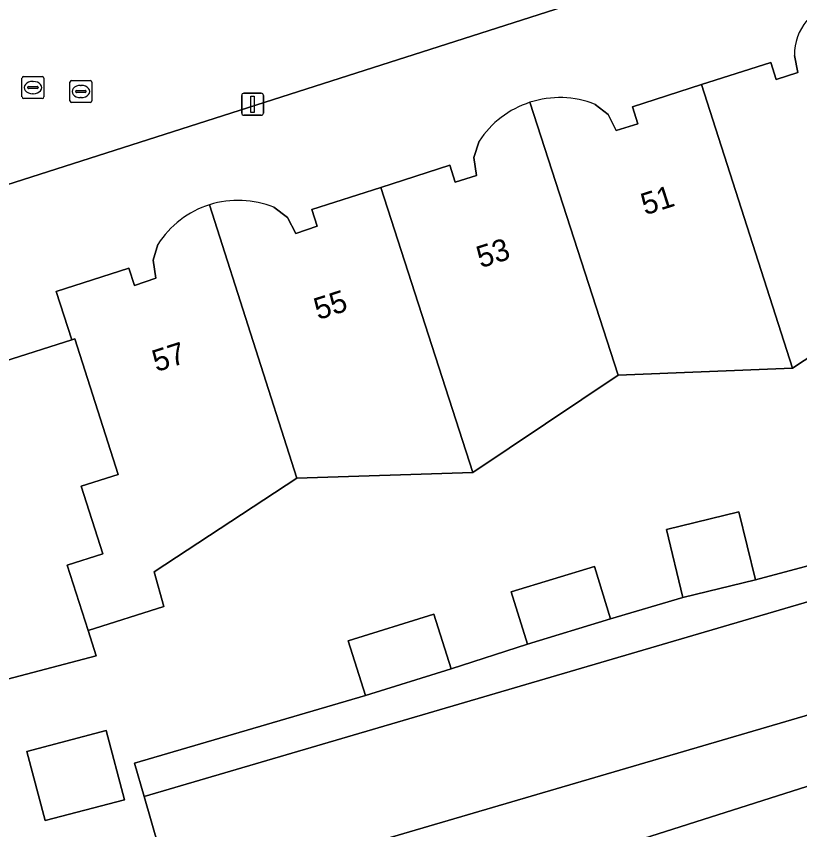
# Model space of a CAD drawing. Extents: x 159499 to 160349, y 382524 to 383273.
# Drawn here: x 159667.59 to 159703.39, y 382799.52 to 382836.7 of the extents above; entities that cross this region are included whole.
import ezdxf

# ---------------------------------------------------------------- set-up
doc = ezdxf.new("R2010")
doc.units = 0
for name, color, linetype in [('IMGEO_Erf', 7, 'Continuous'), ('IMGEO_Groenvoorziening', 7, 'Continuous'), ('IMGEO_Lichtmast', 7, 'Continuous'), ('IMGEO_Pand', 7, 'Continuous'), ('IMGEO_Pand_nummerreeks', 7, 'Continuous'), ('IMGEO_Rijbaan_lokaal_open', 7, 'Continuous'), ('IMGEO_Rioolput', 7, 'Continuous'), ('IMGEO_Voetpad_open', 7, 'Continuous')]:
    doc.layers.add(name, color=color, linetype=linetype)

msp = doc.modelspace()

# ---------------------------------------------------------------- linework, layer by layer
at = {"layer": 'IMGEO_Erf'}
for points in [[(159706.174, 382845.013), (159707.207, 382841.819), (159705.912, 382841.405), (159664.868, 382828.266), (159663.864, 382831.383), (159666.542, 382832.265), (159661.739, 382847.267), (159659.033, 382846.414), (159658.047, 382849.524), (159699.119, 382862.705), (159700.405, 382863.118), (159700.812, 382861.848)], [(159660.525, 382835.656), (159660.06, 382835.05), (159659.319, 382834.671), (159659.644, 382833.689), (159660.417, 382833.93), (159661.452, 382830.613), (159656.347, 382828.991), (159657.362, 382825.93), (159658.83, 382826.406), (159662.712, 382824.41), (159666.599, 382822.412), (159667.071, 382820.931), (159670.133, 382821.912), (159669.419, 382824.112), (159672.736, 382825.178), (159672.993, 382824.399), (159673.966, 382824.727), (159673.846, 382825.549), (159674.066, 382826.268)], [(159707.609, 382835.645), (159708.389, 382833.209), (159709.618, 382829.381), (159710.852, 382829.78), (159711.62, 382826.368), (159709.687, 382825.745), (159709.894, 382825.104), (159703.068, 382820.615), (159695.103, 382820.291), (159688.451, 382815.846), (159680.409, 382815.596)], [(159694.044, 382832.671), (159694.639, 382832.203), (159695.009, 382831.47), (159695.989, 382831.786), (159695.755, 382832.562), (159698.909, 382833.574), (159702.064, 382834.586), (159702.321, 382833.811), (159703.309, 382834.124), (159703.146, 382834.908)], [(159679.369, 382827.966), (159679.991, 382827.497), (159680.368, 382826.773), (159681.349, 382827.105), (159681.104, 382827.867), (159684.248, 382828.877), (159687.411, 382829.894), (159687.648, 382829.112), (159688.624, 382829.415), (159688.5, 382830.239), (159688.738, 382830.986)], [(159680.409, 382815.596), (159673.89, 382811.313), (159674.339, 382809.721), (159670.881, 382808.621), (159671.251, 382807.474), (159666.907, 382806.328), (159665.465, 382812.52)], [(159707.693, 382805.912), (159674.81, 382796.272), (159673.434, 382801.05), (159672.996, 382802.571), (159683.545, 382805.66), (159682.766, 382808.151), (159686.68, 382809.374), (159687.458, 382806.883), (159690.946, 382808.003), (159690.213, 382810.393), (159694.007, 382811.556), (159694.74, 382809.166), (159698.054, 382810.135), (159697.297, 382813.244), (159700.608, 382814.05), (159701.365, 382810.94), (159705.812, 382812.13)], [(159682.294, 382794.673), (159705.767, 382802.152), (159710.531, 382803.67), (159711.953, 382799.207), (159726.792, 382803.935), (159729.084, 382796.741)]]:
    msp.add_lwpolyline(points, dxfattribs=at)
msp.add_lwpolyline([(159668.916, 382799.943), (159668.084, 382803.101), (159671.699, 382804.055), (159672.532, 382800.897)], close=True, dxfattribs=at)
for centre, radius, start, end in [((159705.588, 382834.927), 2.442, 140.0081, 180.4376), ((159692.426, 382828.578), 4.401, 68.4311, 107.9903), ((159692.424, 382828.572), 4.406, 107.937, 146.7806), ((159677.732, 382823.945), 4.34, 107.475, 147.6411), ((159677.734, 382823.941), 4.344, 67.8876, 107.4767)]:
    msp.add_arc(centre, radius, start, end, dxfattribs=at)
at = {"layer": 'IMGEO_Groenvoorziening'}
msp.add_lwpolyline([(159742.845, 382815.409), (159741.322, 382820.139), (159729.3, 382816.347), (159706.393, 382810.712), (159673.434, 382801.05), (159674.81, 382796.272), (159707.693, 382805.912), (159730.6, 382811.547)], close=True, dxfattribs=at)
at = {"layer": 'IMGEO_Lichtmast'}
for p, q in [((159677.894, 382832.276), (159677.894, 382833.076)), ((159677.894, 382833.076), (159677.894, 382832.276)), ((159677.994, 382833.176), (159678.784, 382833.176)), ((159678.784, 382833.176), (159677.994, 382833.176)), ((159678.884, 382833.076), (159678.884, 382832.276)), ((159678.884, 382832.276), (159678.884, 382833.076)), ((159678.784, 382832.176), (159677.994, 382832.176)), ((159677.994, 382832.176), (159678.784, 382832.176))]:
    msp.add_line(p, q, dxfattribs=at)
msp.add_lwpolyline([(159678.314, 382833.051), (159678.464, 382833.051), (159678.464, 382832.301), (159678.314, 382832.301), (159678.314, 382833.051)], dxfattribs=at)
for centre, start, end in [((159677.994, 382833.076), 90, 180), ((159677.994, 382833.076), 90, 180), ((159678.784, 382833.076), 0, 90), ((159678.784, 382833.076), 360, 90), ((159677.994, 382832.276), 180, 270), ((159677.994, 382832.276), 180, 270), ((159678.784, 382832.276), 270, 0), ((159678.784, 382832.276), 270, 0)]:
    msp.add_arc(centre, 0.1, start, end, dxfattribs=at)
at = {"layer": 'IMGEO_Pand'}
for points in [[(159703.146, 382834.908), (159703.309, 382834.124), (159702.321, 382833.811), (159702.064, 382834.586), (159698.909, 382833.574), (159703.068, 382820.615), (159709.894, 382825.104), (159709.687, 382825.745), (159708.618, 382829.058), (159709.618, 382829.381), (159708.389, 382833.209)], [(159691.067, 382832.764), (159695.103, 382820.291), (159703.068, 382820.615), (159698.909, 382833.574), (159695.755, 382832.562), (159695.989, 382831.786), (159695.009, 382831.47), (159694.639, 382832.203), (159694.044, 382832.671)], [(159688.738, 382830.986), (159688.5, 382830.239), (159688.624, 382829.415), (159687.648, 382829.112), (159687.411, 382829.894), (159684.248, 382828.877), (159688.451, 382815.846), (159695.103, 382820.291), (159691.067, 382832.764)], [(159676.429, 382828.085), (159680.409, 382815.596), (159688.451, 382815.846), (159684.248, 382828.877), (159681.104, 382827.867), (159681.349, 382827.105), (159680.368, 382826.773), (159679.991, 382827.497), (159679.369, 382827.966)], [(159674.066, 382826.268), (159673.846, 382825.549), (159673.966, 382824.727), (159672.993, 382824.399), (159672.736, 382825.178), (159669.419, 382824.112), (159670.133, 382821.912), (159670.276, 382821.958), (159672.248, 382815.759), (159670.561, 382815.223), (159671.543, 382812.138), (159669.914, 382811.62), (159670.881, 382808.621), (159674.339, 382809.721), (159673.89, 382811.313), (159680.409, 382815.596), (159676.429, 382828.085)], [(159665.465, 382812.52), (159666.907, 382806.328), (159671.251, 382807.474), (159670.881, 382808.621), (159669.914, 382811.62), (159671.543, 382812.138), (159670.561, 382815.223), (159672.248, 382815.759), (159670.276, 382821.958), (159670.133, 382821.912), (159667.071, 382820.931), (159666.599, 382822.412), (159662.712, 382824.41), (159657.049, 382813.325)], [(159729.084, 382796.741), (159726.792, 382803.935), (159711.953, 382799.207), (159710.531, 382803.67), (159705.767, 382802.152), (159682.294, 382794.673)]]:
    msp.add_lwpolyline(points, dxfattribs=at)
for points in [[(159698.054, 382810.135), (159701.365, 382810.94), (159700.608, 382814.05), (159697.297, 382813.244)], [(159690.946, 382808.003), (159694.74, 382809.166), (159694.007, 382811.556), (159690.213, 382810.393)], [(159683.545, 382805.66), (159687.458, 382806.883), (159686.68, 382809.374), (159682.766, 382808.151)], [(159668.916, 382799.943), (159672.532, 382800.897), (159671.699, 382804.055), (159668.084, 382803.101)]]:
    msp.add_lwpolyline(points, close=True, dxfattribs=at)
for centre, radius, start, end in [((159705.588, 382834.927), 2.442, 140.0081, 180.4376), ((159692.426, 382828.578), 4.401, 68.4311, 107.9903), ((159692.424, 382828.572), 4.406, 107.937, 146.7806), ((159677.732, 382823.945), 4.34, 107.475, 147.6411), ((159677.734, 382823.941), 4.344, 67.8876, 107.4767)]:
    msp.add_arc(centre, radius, start, end, dxfattribs=at)
at = {"layer": 'IMGEO_Rijbaan_lokaal_open'}
msp.add_lwpolyline([(159699.712, 382860.799), (159699.119, 382862.705), (159658.047, 382849.524), (159659.033, 382846.414), (159661.739, 382847.267), (159666.542, 382832.265), (159663.864, 382831.383), (159664.868, 382828.266), (159705.912, 382841.405), (159704.996, 382844.273)], dxfattribs=at)
at = {"layer": 'IMGEO_Rioolput'}
for p, q in [((159667.856, 382833.012), (159667.856, 382833.864)), ((159667.931, 382833.938), (159668.783, 382833.938)), ((159668.344, 382833.718), (159668.369, 382833.718)), ((159668.857, 382833.864), (159668.857, 382833.012)), ((159670.046, 382832.833), (159670.046, 382833.685)), ((159670.121, 382833.759), (159670.973, 382833.759)), ((159671.047, 382833.685), (159671.047, 382832.833)), ((159668.115, 382833.432), (159668.115, 382833.444)), ((159668.553, 382833.395), (159668.155, 382833.395)), ((159668.158, 382833.481), (159668.556, 382833.481)), ((159668.599, 382833.444), (159668.599, 382833.432)), ((159670.305, 382833.253), (159670.305, 382833.265)), ((159670.348, 382833.302), (159670.746, 382833.302)), ((159670.534, 382833.539), (159670.559, 382833.539)), ((159670.789, 382833.265), (159670.789, 382833.253)), ((159668.783, 382832.938), (159667.931, 382832.938)), ((159668.367, 382833.158), (159668.342, 382833.158)), ((159670.743, 382833.216), (159670.345, 382833.216)), ((159670.557, 382832.979), (159670.532, 382832.979)), ((159670.973, 382832.759), (159670.121, 382832.759))]:
    msp.add_line(p, q, dxfattribs=at)
for points in [[(159667.856, 382833.012), (159667.856, 382833.864)], [(159667.931, 382833.938), (159668.783, 382833.938)], [(159668.857, 382833.864), (159668.857, 382833.012)], [(159670.046, 382832.833), (159670.046, 382833.685)], [(159670.121, 382833.759), (159670.973, 382833.759)], [(159671.047, 382833.685), (159671.047, 382832.833)], [(159668.783, 382832.938), (159667.931, 382832.938)], [(159670.973, 382832.759), (159670.121, 382832.759)]]:
    msp.add_lwpolyline(points, dxfattribs=at)
for centre, radius, start, end in [((159667.933, 382833.862), 0.0765, 91.552, 178.448), ((159667.933, 382833.862), 0.0765, 91.552, 178.448), ((159668.781, 382833.862), 0.0765, 1.552, 88.448), ((159668.781, 382833.862), 0.0765, 1.552, 88.448), ((159670.123, 382833.683), 0.0765, 91.552, 178.448), ((159670.123, 382833.683), 0.0765, 91.552, 178.448), ((159670.971, 382833.683), 0.0765, 1.552, 88.448), ((159670.971, 382833.683), 0.0765, 1.552, 88.448), ((159668.155, 382833.441), 0.0403, 85.8775, 175.7526), ((159668.152, 382833.431), 0.0366, 178.938, 274.7102), ((159668.556, 382833.438), 0.043, 264.8664, 352.4533), ((159668.56, 382833.443), 0.0386, 1.7309, 96.639), ((159670.345, 382833.262), 0.0403, 85.8775, 175.7526), ((159670.342, 382833.252), 0.0366, 178.938, 274.7102), ((159670.746, 382833.259), 0.043, 264.8664, 352.4533), ((159670.75, 382833.264), 0.0386, 1.7309, 96.639), ((159667.933, 382833.014), 0.0765, 181.552, 268.448), ((159667.933, 382833.014), 0.0765, 181.552, 268.448), ((159668.781, 382833.014), 0.0765, 271.552, 358.448), ((159668.781, 382833.014), 0.0765, 271.552, 358.448), ((159670.123, 382832.835), 0.0765, 181.552, 268.448), ((159670.123, 382832.835), 0.0765, 181.552, 268.448), ((159670.971, 382832.835), 0.0765, 271.552, 358.448), ((159670.971, 382832.835), 0.0765, 271.552, 358.448)]:
    msp.add_arc(centre, radius, start, end, dxfattribs=at)
for centre, major_axis, ratio, start_param, end_param in [((159668.343, 382833.438), (-0.387, 0.002), 0.722429, 4.712389, 7.853982), ((159668.368, 382833.438), (-0.39, 0.002), 0.717154, 1.570796, 4.712389), ((159670.533, 382833.259), (-0.387, 0.002), 0.722429, 4.712389, 7.853982), ((159670.558, 382833.259), (-0.39, 0.002), 0.717154, 1.570796, 4.712389)]:
    msp.add_ellipse(centre, major_axis=major_axis, ratio=ratio, start_param=start_param, end_param=end_param, dxfattribs=at)
at = {"layer": 'IMGEO_Voetpad_open'}
msp.add_lwpolyline([(159740.402, 382821.43), (159728.815, 382817.782), (159726.206, 382817.258), (159726.23, 382817.155), (159715.715, 382814.924), (159714.347, 382814.634), (159714.431, 382814.263), (159705.812, 382812.13), (159701.365, 382810.94), (159698.054, 382810.135), (159694.74, 382809.166), (159690.946, 382808.003), (159687.458, 382806.883), (159683.545, 382805.66), (159672.996, 382802.571), (159673.434, 382801.05), (159706.393, 382810.712), (159729.3, 382816.347)], dxfattribs=at)

# ---------------------------------------------------------------- texts
at = {"layer": 'IMGEO_Pand_nummerreeks'}
for s, p in [('51', (159696.327, 382827.595)), ('53', (159688.816, 382825.18)), ('55', (159681.386, 382822.81)), ('57', (159673.999, 382820.432))]:
    msp.add_text(s, height=1, rotation=17.7637, dxfattribs=at).set_placement(p)

doc.saveas('drawing.dxf')
